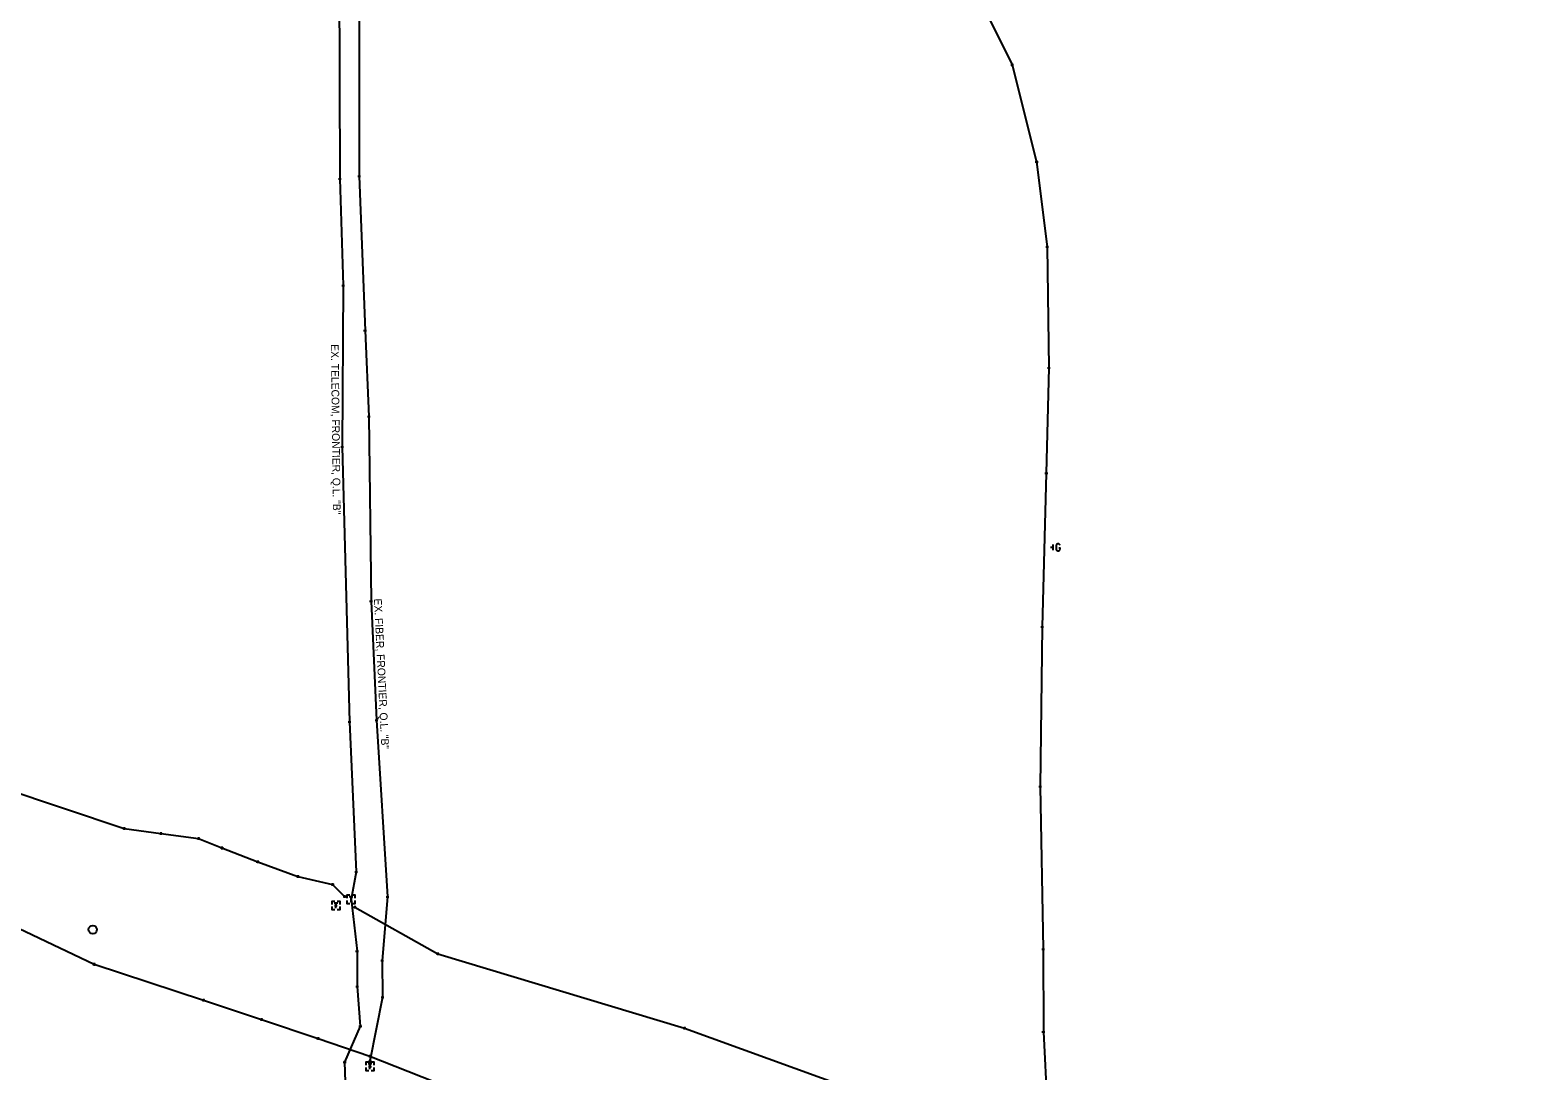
# Model space of a CAD drawing. Extents: x 2046588 to 2048646, y 455919 to 457871.
# Drawn here: x 2047549 to 2048096, y 456951 to 457329 of the extents above; entities that cross this region are included whole.
import ezdxf

# ---------------------------------------------------------------- set-up
doc = ezdxf.new("R2010")
doc.units = 0
for name, color, linetype in [('CM_Corridor_Top_Mesh', 7, 'Continuous'), ('MD_P_Surface_Non-Reinforced_Concrete_Pavement', 7, 'Continuous'), ('UT_P_Gas', 7, 'Continuous'), ('UT_X_FO', 7, 'Continuous'), ('UT_X_Gas', 7, 'Continuous'), ('UT_X_Overhead_Combined', 7, 'Continuous'), ('UT_X_Overhead_Telecom', 7, 'Continuous'), ('UT_X_Telecom_Text', 7, 'Continuous')]:
    doc.layers.add(name, color=color, linetype=linetype)

msp = doc.modelspace()

# ---------------------------------------------------------------- linework, layer by layer
at = {"layer": 'CM_Corridor_Top_Mesh'}
for points in [[(2047648.82, 457629.87), (2047657.02, 457629.62), (2047658.75, 457593.58), (2047659.52, 457521.71), (2047661.21, 457444.24), (2047661.57, 457347.82), (2047661.76, 457274.75), (2047663.01, 457236.05), (2047662.63, 457177.6), (2047665.24, 457077.73), (2047667.68, 457023.38), (2047665.85, 457013.41)], [(2046591.62, 457318.3), (2046634.49, 457314.33), (2046683.6, 457309.26), (2046728.87, 457304.51), (2046756.52, 457301.8), (2046770.98, 457300.11), (2046793.5, 457299.64), (2046823.77, 457296.38), (2046919.05, 457278.1), (2046970.54, 457267.22), (2047006.64, 457256.03), (2047063.52, 457235.76), (2047111.08, 457217.54), (2047158.16, 457199.88), (2047204.68, 457184.45), (2047252.22, 457165.07), (2047295.66, 457149.33), (2047344.75, 457130.49), (2047392.72, 457111.85), (2047443.95, 457091.74), (2047493.09, 457072.16), (2047539.56, 457053.79), (2047583.55, 457039.04), (2047596.82, 457037.26)], [(2047596.82, 457037.26), (2047610.48, 457035.45), (2047619.02, 457032.02), (2047631.98, 457027.02), (2047646.59, 457021.67), (2047659.16, 457018.75), (2047663.46, 457014.45)], [(2047665.85, 457013.41), (2047668, 456994.57), (2047668.07, 456981.81), (2047669.2, 456967.36), (2047663.52, 456954.27), (2047669.97, 456759.3)], [(2047667.24, 457010.56), (2047697.33, 456993.62), (2047786.8, 456966.6), (2047857.15, 456941.14), (2047942.17, 456911.18), (2048015.15, 456885.28), (2048069.44, 456866.41), (2048172.16, 456826.67), (2048228.9, 456807.13), (2048277.95, 456789.73), (2048347.98, 456763.63), (2048445.37, 456729.99), (2048495.85, 456709.95), (2048575.59, 456682.31), (2048645.25, 456657.54)]]:
    msp.add_lwpolyline(points, dxfattribs=at)
at = {"layer": 'UT_P_Gas'}
for p, q in [((2047659.7, 457012.14), (2047661, 457012.14)), ((2047660.35, 457010.14), (2047660.35, 457012.14)), ((2047665.2, 457014.41), (2047666.5, 457014.41)), ((2047665.85, 457012.41), (2047665.85, 457014.41)), ((2047665.85, 457013.41), (2047665.85, 457013.41)), ((2047660.35, 457011.14), (2047660.35, 457011.14)), ((2047672.06, 456953.78), (2047673.36, 456953.78)), ((2047672.71, 456951.78), (2047672.71, 456953.78)), ((2047672.71, 456952.78), (2047672.71, 456952.78))]:
    msp.add_line(p, q, dxfattribs=at)
for points in [[(2047659.95, 457012.64), (2047658.85, 457012.64), (2047658.85, 457011.54)], [(2047661.85, 457011.54), (2047661.85, 457012.64), (2047660.75, 457012.64)], [(2047665.45, 457014.91), (2047664.35, 457014.91), (2047664.35, 457013.81)], [(2047664.35, 457013.01), (2047664.35, 457011.91), (2047665.45, 457011.91)], [(2047667.35, 457013.81), (2047667.35, 457014.91), (2047666.25, 457014.91)], [(2047666.25, 457011.91), (2047667.35, 457011.91), (2047667.35, 457013.01)], [(2047658.85, 457010.74), (2047658.85, 457009.64), (2047659.95, 457009.64)], [(2047660.75, 457009.64), (2047661.85, 457009.64), (2047661.85, 457010.74)], [(2047672.31, 456954.28), (2047671.21, 456954.28), (2047671.21, 456953.18)], [(2047671.21, 456952.38), (2047671.21, 456951.28), (2047672.31, 456951.28)], [(2047674.21, 456953.18), (2047674.21, 456954.28), (2047673.11, 456954.28)], [(2047673.11, 456951.28), (2047674.21, 456951.28), (2047674.21, 456952.38)]]:
    msp.add_lwpolyline(points, dxfattribs=at)
at = {"layer": 'UT_X_FO'}
for p, q in [((2047920.55, 457141.09), (2047919.6, 457141.09)), ((2047920.55, 457140.09), (2047920.55, 457142.09))]:
    msp.add_line(p, q, dxfattribs=at)
msp.add_lwpolyline([(2047923.02, 457141.84), (2047923, 457141.94), (2047922.95, 457142.04), (2047922.85, 457142.14), (2047922.71, 457142.26), (2047922.61, 457142.3), (2047922.53, 457142.32), (2047922.41, 457142.34), (2047922.18, 457142.34), (2047922.08, 457142.32), (2047922.02, 457142.3), (2047921.94, 457142.26), (2047921.78, 457142.14), (2047921.69, 457142), (2047921.63, 457141.84), (2047921.59, 457141.63), (2047921.55, 457141.31), (2047921.55, 457140.9), (2047921.57, 457140.56), (2047921.65, 457140.31), (2047921.76, 457140.07), (2047921.86, 457139.99), (2047921.98, 457139.91), (2047922.2, 457139.84), (2047922.41, 457139.84), (2047922.63, 457139.87), (2047922.71, 457139.91), (2047922.79, 457139.95), (2047922.87, 457140.03), (2047922.95, 457140.15), (2047923.02, 457140.33), (2047923.02, 457140.82), (2047922.61, 457140.82)], dxfattribs=at)
at = {"layer": 'UT_X_Gas'}
for p, q in [((2047905.15, 457316.11), (2047906.15, 457316.11)), ((2047905.65, 457316.61), (2047905.65, 457315.61)), ((2047905.65, 457316.11), (2047905.65, 457316.11)), ((2047914.03, 457280.99), (2047915.03, 457280.99)), ((2047914.53, 457281.49), (2047914.53, 457280.49)), ((2047914.53, 457280.99), (2047914.53, 457280.99)), ((2047661.26, 457274.75), (2047662.26, 457274.75)), ((2047661.76, 457275.25), (2047661.76, 457274.25)), ((2047661.76, 457274.75), (2047661.76, 457274.75)), ((2047668.28, 457275.83), (2047669.28, 457275.83)), ((2047668.78, 457276.33), (2047668.78, 457275.33)), ((2047668.78, 457275.83), (2047668.78, 457275.83)), ((2047917.81, 457250.15), (2047918.81, 457250.15)), ((2047918.31, 457250.65), (2047918.31, 457249.65)), ((2047918.31, 457250.15), (2047918.31, 457250.15)), ((2047663.01, 457236.55), (2047663.01, 457235.55)), ((2047662.51, 457236.05), (2047663.51, 457236.05)), ((2047663.01, 457236.05), (2047663.01, 457236.05)), ((2047670.4, 457219.79), (2047671.4, 457219.79)), ((2047670.9, 457220.29), (2047670.9, 457219.29)), ((2047670.9, 457219.79), (2047670.9, 457219.79)), ((2047918.41, 457206.27), (2047919.41, 457206.27)), ((2047918.91, 457206.77), (2047918.91, 457205.77)), ((2047918.91, 457206.27), (2047918.91, 457206.27)), ((2047671.79, 457188.61), (2047672.79, 457188.61)), ((2047672.29, 457189.11), (2047672.29, 457188.11)), ((2047672.29, 457188.61), (2047672.29, 457188.61)), ((2047662.13, 457177.6), (2047663.13, 457177.6)), ((2047662.63, 457178.1), (2047662.63, 457177.1)), ((2047662.63, 457177.6), (2047662.63, 457177.6)), ((2047917.54, 457168.01), (2047918.54, 457168.01)), ((2047918.04, 457168.51), (2047918.04, 457167.51)), ((2047918.04, 457168.01), (2047918.04, 457168.01)), ((2047672.59, 457121.54), (2047673.59, 457121.54)), ((2047673.09, 457122.04), (2047673.09, 457121.04)), ((2047673.09, 457121.54), (2047673.09, 457121.54)), ((2047916.01, 457112.29), (2047917.01, 457112.29)), ((2047916.51, 457112.79), (2047916.51, 457111.79)), ((2047916.51, 457112.29), (2047916.51, 457112.29)), ((2047664.74, 457077.73), (2047665.74, 457077.73)), ((2047665.24, 457078.23), (2047665.24, 457077.23)), ((2047665.24, 457077.73), (2047665.24, 457077.73)), ((2047674.59, 457078.33), (2047675.59, 457078.33)), ((2047675.09, 457078.83), (2047675.09, 457077.83)), ((2047675.09, 457078.33), (2047675.09, 457078.33)), ((2047915.3, 457054.38), (2047916.3, 457054.38)), ((2047915.8, 457054.88), (2047915.8, 457053.88)), ((2047915.8, 457054.38), (2047915.8, 457054.38)), ((2047583.55, 457039.54), (2047583.55, 457038.54)), ((2047583.05, 457039.04), (2047584.05, 457039.04)), ((2047583.55, 457039.04), (2047583.55, 457039.04)), ((2047596.32, 457037.26), (2047597.32, 457037.26)), ((2047596.82, 457037.76), (2047596.82, 457036.76)), ((2047596.82, 457037.26), (2047596.82, 457037.26)), ((2047609.98, 457035.45), (2047610.98, 457035.45)), ((2047610.48, 457035.95), (2047610.48, 457034.95)), ((2047610.48, 457035.45), (2047610.48, 457035.45)), ((2047618.52, 457032.02), (2047619.52, 457032.02)), ((2047619.02, 457032.52), (2047619.02, 457031.52)), ((2047619.02, 457032.02), (2047619.02, 457032.02)), ((2047631.48, 457027.02), (2047632.48, 457027.02)), ((2047631.98, 457027.52), (2047631.98, 457026.52)), ((2047631.98, 457027.02), (2047631.98, 457027.02)), ((2047667.18, 457023.38), (2047668.18, 457023.38)), ((2047667.68, 457023.88), (2047667.68, 457022.88)), ((2047667.68, 457023.38), (2047667.68, 457023.38)), ((2047646.09, 457021.67), (2047647.09, 457021.67)), ((2047646.59, 457022.17), (2047646.59, 457021.17)), ((2047646.59, 457021.67), (2047646.59, 457021.67)), ((2047658.66, 457018.75), (2047659.66, 457018.75)), ((2047659.16, 457019.25), (2047659.16, 457018.25)), ((2047659.16, 457018.75), (2047659.16, 457018.75)), ((2047662.96, 457014.45), (2047663.96, 457014.45)), ((2047663.46, 457014.95), (2047663.46, 457013.95)), ((2047663.46, 457014.45), (2047663.46, 457014.45)), ((2047678.58, 457014.24), (2047679.58, 457014.24)), ((2047679.08, 457014.74), (2047679.08, 457013.74)), ((2047679.08, 457014.24), (2047679.08, 457014.24)), ((2047659.85, 457011.14), (2047660.85, 457011.14)), ((2047660.35, 457011.64), (2047660.35, 457010.64)), ((2047660.35, 457011.14), (2047660.35, 457011.14)), ((2047666.74, 457010.56), (2047667.74, 457010.56)), ((2047667.24, 457011.06), (2047667.24, 457010.06)), ((2047667.24, 457010.56), (2047667.24, 457010.56)), ((2047916.89, 456995.77), (2047916.89, 456994.77)), ((2047572.61, 456990.31), (2047572.61, 456989.31)), ((2047667.5, 456994.57), (2047668.5, 456994.57)), ((2047668, 456995.07), (2047668, 456994.07)), ((2047668, 456994.57), (2047668, 456994.57)), ((2047676.63, 456991.2), (2047677.63, 456991.2)), ((2047677.13, 456991.7), (2047677.13, 456990.7)), ((2047677.13, 456991.2), (2047677.13, 456991.2)), ((2047696.83, 456993.62), (2047697.83, 456993.62)), ((2047697.33, 456994.12), (2047697.33, 456993.12)), ((2047697.33, 456993.62), (2047697.33, 456993.62)), ((2047916.39, 456995.27), (2047917.39, 456995.27)), ((2047916.89, 456995.27), (2047916.89, 456995.27)), ((2047572.11, 456989.81), (2047573.11, 456989.81)), ((2047572.61, 456989.81), (2047572.61, 456989.81)), ((2047667.57, 456981.81), (2047668.57, 456981.81)), ((2047668.07, 456982.31), (2047668.07, 456981.31)), ((2047668.07, 456981.81), (2047668.07, 456981.81)), ((2047611.83, 456976.78), (2047612.83, 456976.78)), ((2047612.33, 456977.28), (2047612.33, 456976.28)), ((2047612.33, 456976.78), (2047612.33, 456976.78)), ((2047676.75, 456977.91), (2047677.75, 456977.91)), ((2047677.25, 456978.41), (2047677.25, 456977.41)), ((2047677.25, 456977.91), (2047677.25, 456977.91)), ((2047632.85, 456969.75), (2047633.85, 456969.75)), ((2047633.35, 456970.25), (2047633.35, 456969.25)), ((2047633.35, 456969.75), (2047633.35, 456969.75)), ((2047653.35, 456962.85), (2047654.35, 456962.85)), ((2047653.85, 456963.35), (2047653.85, 456962.35)), ((2047653.85, 456962.85), (2047653.85, 456962.85)), ((2047668.7, 456967.36), (2047669.7, 456967.36)), ((2047669.2, 456967.86), (2047669.2, 456966.86)), ((2047669.2, 456967.36), (2047669.2, 456967.36)), ((2047786.3, 456966.6), (2047787.3, 456966.6)), ((2047786.8, 456967.1), (2047786.8, 456966.1)), ((2047786.8, 456966.6), (2047786.8, 456966.6)), ((2047916.46, 456965.32), (2047917.46, 456965.32)), ((2047916.96, 456965.82), (2047916.96, 456964.82)), ((2047916.96, 456965.32), (2047916.96, 456965.32)), ((2047663.02, 456954.27), (2047664.02, 456954.27)), ((2047663.52, 456954.77), (2047663.52, 456953.77)), ((2047663.52, 456954.27), (2047663.52, 456954.27)), ((2047672.12, 456956.44), (2047673.12, 456956.44)), ((2047672.21, 456954.72), (2047673.21, 456954.72)), ((2047672.21, 456952.78), (2047673.21, 456952.78)), ((2047672.62, 456956.94), (2047672.62, 456955.94)), ((2047672.62, 456956.44), (2047672.62, 456956.44)), ((2047672.71, 456955.22), (2047672.71, 456954.22)), ((2047672.71, 456954.72), (2047672.71, 456954.72)), ((2047672.71, 456953.28), (2047672.71, 456952.28)), ((2047672.71, 456952.78), (2047672.71, 456952.78))]:
    msp.add_line(p, q, dxfattribs=at)
at = {"layer": 'UT_X_Overhead_Combined'}
for points in [[(2047658.6, 457870.23), (2047659.87, 457843.86), (2047659.6, 457800.01), (2047658.98, 457745.74), (2047662.27, 457688.03), (2047665.36, 457642.02), (2047665.36, 457611.98), (2047666.58, 457552.89), (2047668.01, 457521.56), (2047668, 457443.89), (2047668.58, 457385.81), (2047668.83, 457339.7), (2047668.78, 457275.83), (2047670.9, 457219.79), (2047672.29, 457188.61), (2047673.09, 457121.54), (2047675.09, 457078.33), (2047679.08, 457014.24), (2047677.13, 456991.2), (2047677.25, 456977.91), (2047672.71, 456954.72)], [(2047535.14, 457007.65), (2047572.61, 456989.81), (2047612.33, 456976.78), (2047633.35, 456969.75), (2047653.85, 456962.85), (2047672.62, 456956.44), (2047705.37, 456943.59), (2047757.77, 456924.93), (2047786.86, 456915.85), (2047838.55, 456897.47), (2047879.66, 456882.22), (2047909.65, 456870.7), (2047946.65, 456857.43), (2047980.46, 456846.8), (2048022.1, 456832.89), (2048064.85, 456816.32), (2048107.79, 456798.87)]]:
    msp.add_lwpolyline(points, dxfattribs=at)
at = {"layer": 'UT_X_Overhead_Telecom'}
for points in [[(2047873.14, 457379.17), (2047890.27, 457347.12), (2047905.65, 457316.11), (2047914.53, 457280.99), (2047918.31, 457250.15), (2047918.91, 457206.27), (2047918.04, 457168.01), (2047916.51, 457112.29)], [(2047916.51, 457112.29), (2047915.8, 457054.38), (2047916.89, 456995.27), (2047916.96, 456965.32), (2047918.33, 456938.4), (2047920.4, 456874.65), (2047922.67, 456833.39)]]:
    msp.add_lwpolyline(points, dxfattribs=at)
at = {"layer": 'UT_X_Telecom_Text'}
msp.add_circle((2047572.15, 457002.4), 1.5, dxfattribs=at)

# ---------------------------------------------------------------- texts
at = {"layer": 'MD_P_Surface_Non-Reinforced_Concrete_Pavement'}
for s, rotation, p in [('EX. TELECOM, FRONTIER, Q.L. "B"', 270.7031, (2047658.53, 457214.77)), ('EX. FIBER, FRONTIER, Q.L. "B"', 272.8135, (2047674.16, 457122.45))]:
    msp.add_text(s, height=2.8, rotation=rotation, dxfattribs=at).set_placement(p)

doc.saveas('drawing.dxf')
